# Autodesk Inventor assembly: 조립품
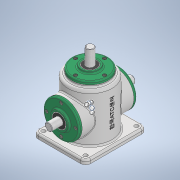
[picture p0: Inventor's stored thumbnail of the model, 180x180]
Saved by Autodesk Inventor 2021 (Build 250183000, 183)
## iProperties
Created: 2021-02
Part Number: 조립품
Document SubType Name: Assembly
Designer: 201-05
Author: 201-05
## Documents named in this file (16)
- C:\Users\201-05\Desktop\710215V1004\조립품.iam
- C:\Users\201-05\Desktop\710215V1004\본체.ipt
- C:\Users\201-05\Desktop\710215V1004\커버.ipt
- C:\Users\201-05\Desktop\710215V1004\베어링 6203.ipt
- C:\Users\201-05\Desktop\710215V1004\볼트 M4.ipt
- 볼트 M4.ipt
- C:\Users\201-05\Desktop\710215V1004\오일 실.ipt
- 오일 실.ipt
- C:\Users\201-05\Desktop\710215V1004\메인 축.ipt
- 메인 축.ipt
- C:\Users\201-05\Desktop\710215V1004\키 5x5.ipt
- C:\Users\201-05\Desktop\710215V1004\메인 베벨기어.ipt
- C:\Users\201-05\Desktop\710215V1004\서브 축.ipt
- 서브 축.ipt
- C:\Users\201-05\Desktop\710215V1004\키 4x4.ipt
- C:\Users\201-05\Desktop\710215V1004\서브 베벨기어.ipt
